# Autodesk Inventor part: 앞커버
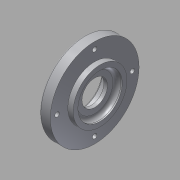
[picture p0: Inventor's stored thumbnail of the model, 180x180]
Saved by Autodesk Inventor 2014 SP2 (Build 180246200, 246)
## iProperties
Created: 2015-09
Part Number: 앞커버
Material: 알루미늄 6061
Document SubType Name: Modeling
Designer: mduedu
Density: 1 g/cm^3
Appearance: 알루미늄 - 평지
Author: mduedu
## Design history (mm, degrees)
sketch "스케치1"
  geometry: L1 (-8, 67)-(-12, 67); L2 (-12, 67)-(-12, 80); L3 (-12, 80)-(-20, 80); L4 (-20, 80)-(-20, 70.5); L5 (-23, 70.5)-(-23, 56.5); L6 (-23, 56.5)-(-8, 56.5); L7 (-8, 56.5)-(-8, 67); L8 (-79.5, 39.5)-(-79.5, 54.5) reference; L9 (48.5, 54.5)-(48.5, 39.5) reference; L10 (-79.5, 47)-(48.5, 47); L11 (-20, 70.5)-(-23, 70.5); 3 further points
  constraints: 18 end point, 6 parallel, 4 midpoint, 1 horizontal, 1 perpendicular, 1 vertical alignment
  dimensions: "d0" = 15 distance between parallel lines of L7 L5; "d2" = 19 diameter of L6 L10; "d3" = 40 diameter of L1 L10; "d5" = 4 distance of L1.start L1.end; "d6" = 66 diameter of L3 L10; "d7" = 8 distance of L2.end L3.end; "d8" = 47 diameter of L4.end L10
revolve "회전1" sketch "스케치1" stored, may be unused: angle "d4" = 90 deg
sketch "스케치2"
  geometry: C1 r 33 at (0, 0) reference; 2 further points
  constraints: 1 coincident
hole "구멍1" sketch "스케치2" at (0, 0) diameter "d11" = 33; stored, may be unused: countersink angle "d15" = 90 deg, drill point angle "d17" = 0 deg; dims "d12" = 6, "d13" = 4, "d14" = 2, "d16" = 4
fillet "모깎기1" dims "d18" = 3
fillet "모깎기2" dims "d19" = 1
sketch "스케치3"
  geometry: C1 r 33 at (0, 0) reference; 2 further points
  constraints: 1 coincident
hole "구멍2" sketch "스케치3" at (0, 0) diameter "d20" = 32; stored, may be unused: countersink angle "d24" = 90 deg, drill point angle "d26" = 0 deg; dims "d21" = 6, "d22" = 4, "d23" = 2, "d25" = 8.3
fillet "모깎기3" dims "d27" = 0.3
chamfer "모따기1" distance "d28" = 0.8; stored, may be unused: second distance "d29" = 2, angle "d30" = 30 deg
sketch "스케치4" dims "d31" = 56
  geometry: C1 r 33 at (0, 0) reference; 6 further points
  constraints: 2 vertical alignment, 1 coincident, 7 other
  dimensions: "d36" = 360 deg dimension on C1.centre point (0, 28) (derived)
sketch "스케치7"
  geometry: 4 further points
hole "구멍4" sketch "스케치7" at (0, 28), (-28, 0), (28, 0), (0, -28) diameter "d48" = 3.4; stored, may be unused: countersink angle "d52" = 90 deg, drill point angle "d54" = 0 deg; dims "d49" = 6, "d50" = 6.5, "d51" = 3.4, "d53" = 8
node "솔리드1"
node "참조1"
node "참조2"
